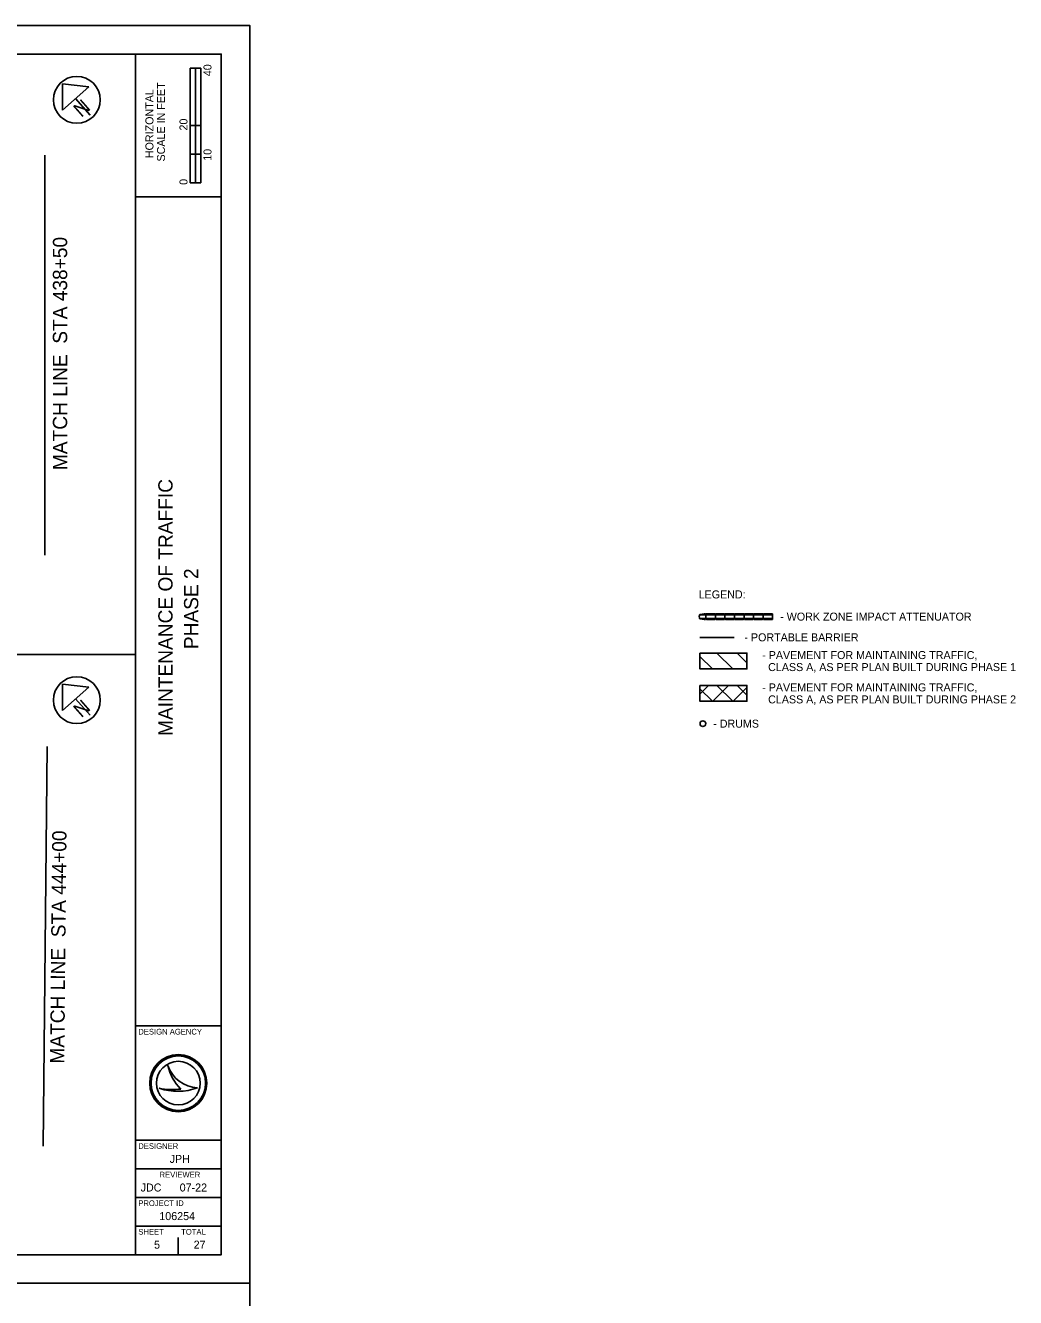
# Model space of a CAD drawing. Extents: x 0 to 5770, y -1320 to 440.
# Drawn here: x 601.5 to 948, y -5 to 440 of the extents above; entities that cross this region are included whole.
import ezdxf

# ---------------------------------------------------------------- set-up
doc = ezdxf.new("R2010")
doc.units = 0
for name, color, linetype in [('_CIVIL_CONSTRUCTION', 7, 'Continuous'), ('BR_X_Sub_Backwall', 7, 'Continuous'), ('GE_P_Alignment', 7, 'Continuous'), ('GE_P_Alignment_100_Bearings', 7, 'Continuous'), ('GE_P_Alignment_100_Cardinal_Points', 7, 'Continuous'), ('GE_P_Alignment_100_Curve_Data', 7, 'Continuous'), ('GE_P_Alignment_100_Stations', 7, 'Continuous'), ('HY_X_Water_Edge', 7, 'Continuous'), ('PV_X_EOP', 7, 'Continuous')]:
    doc.layers.add(name, color=color, linetype=linetype)

msp = doc.modelspace()

# ---------------------------------------------------------------- linework, layer by layer
at = {"layer": '_CIVIL_CONSTRUCTION'}
for points in [[(0, 0), (680, 0), (680, 440), (0, 440)], [(0, -440), (680, -440), (680, 0), (0, 0)]]:
    msp.add_lwpolyline(points, close=True, dxfattribs=at)
at = {"layer": 'BR_X_Sub_Backwall'}
msp.add_line((849.52, 225.95), (837.52, 225.95), dxfattribs=at)
at = {"layer": 'GE_P_Alignment'}
for p, q in [((640, 10), (640, 430)), ((640, 380), (670, 380)), ((640, 90), (670, 90)), ((640, 50), (670, 50)), ((640, 40), (670, 40)), ((640, 30), (670, 30)), ((640, 20), (670, 20))]:
    msp.add_line(p, q, dxfattribs=at)
msp.add_lwpolyline([(30, 430), (670, 430), (670, 10), (30, 10)], close=True, dxfattribs=at)
at = {"layer": 'GE_P_Alignment_100_Bearings'}
for p, q in [((659.13, 385), (659.13, 425)), ((662.88, 425), (659.13, 425)), ((659.13, 405), (659.13, 425)), ((659.13, 425), (661, 425)), ((661, 425), (661.02, 425)), ((661.02, 425), (661.02, 405)), ((662.88, 425), (662.88, 385)), ((661.02, 405), (659.13, 405)), ((662.87, 405), (661, 405)), ((661, 405), (661, 395)), ((662.87, 395), (662.87, 405)), ((661, 395), (659.13, 395)), ((659.13, 395), (659.13, 385)), ((661, 385), (661, 395)), ((661, 395), (662.87, 395)), ((662.88, 385), (659.13, 385)), ((659.13, 385), (661, 385)), ((651.35, 76.19), (651.35, 76.19)), ((648.34, 68.19), (648.34, 68.19)), ((655, 70), (655, 70)), ((661.75, 68.37), (661.75, 68.37)), ((647.5, 13.5), (647.5, 13.5)), ((655, 10), (655, 16))]:
    msp.add_line(p, q, dxfattribs=at)
for radius in [10, 9.54, 9.54, 7.64]:
    msp.add_circle((655, 70), radius, dxfattribs=at)
for centre, radius, start, end in [((662.32, 79.95), 11.6, 198.9257, 198.9319), ((666.93, 79.4), 15.91, 191.6379, 191.6421), ((662.32, 79.95), 11.6, 198.9319, 267.1657), ((666.93, 79.4), 15.91, 191.6421, 226.0947), ((654.79, 87.4), 20.26, 251.4576, 290.0832), ((652.96, 93.09), 25.32, 259.4964, 259.4995), ((654.79, 87.4), 20.26, 251.4527, 251.4576), ((652.96, 93.09), 25.32, 259.4995, 276.6672)]:
    msp.add_arc(centre, radius, start, end, dxfattribs=at)
at = {"layer": 'GE_P_Alignment_100_Cardinal_Points'}
for p, q in [((614.53, 419.6), (614.42, 410.41)), ((614.42, 410.41), (623.66, 418.54)), ((623.66, 418.54), (614.53, 419.6)), ((619.04, 414.48), (624.15, 408.67)), ((30, 220), (640, 220)), ((614.53, 209.6), (614.42, 200.41)), ((623.66, 208.54), (614.53, 209.6)), ((614.42, 200.41), (623.66, 208.54)), ((619.04, 204.48), (624.15, 198.67))]:
    msp.add_line(p, q, dxfattribs=at)
for centre in [(619.47, 413.99), (619.47, 203.99)]:
    msp.add_circle(centre, 8.2, dxfattribs=at)
at = {"layer": 'GE_P_Alignment_100_Curve_Data'}
for p, q in [((608.28, 394.64), (608.28, 254.64)), ((607.71, 47.99), (609.09, 187.71))]:
    msp.add_line(p, q, dxfattribs=at)
for points in [[(837.52, 220.42), (853.95, 220.42), (853.95, 214.88), (837.52, 214.88)], [(837.52, 209.11), (853.95, 209.11), (853.95, 203.57), (837.52, 203.57)]]:
    msp.add_lwpolyline(points, close=True, dxfattribs=at)
at = {"layer": 'GE_P_Alignment_100_Stations'}
for p, q in [((837.52, 219.3), (841.94, 214.88)), ((843.48, 220.42), (849.01, 214.88)), ((850.55, 220.42), (853.95, 217.01)), ((837.52, 206.11), (840.52, 209.11)), ((837.52, 207.99), (841.94, 203.57)), ((842.06, 203.57), (847.59, 209.11)), ((843.48, 209.11), (849.01, 203.57)), ((849.13, 203.57), (853.95, 208.4)), ((850.55, 209.11), (853.95, 205.7))]:
    msp.add_line(p, q, dxfattribs=at)
at = {"layer": 'HY_X_Water_Edge'}
for centre in [(619.47, 413.99), (619.47, 203.99)]:
    msp.add_circle(centre, 8.2, dxfattribs=at)
at = {"layer": 'PV_X_EOP'}
for p, q in [((837.47, 233.87), (862.96, 233.87)), ((862.96, 232.54), (837.47, 232.54)), ((839.02, 234.2), (837.52, 233.95)), ((839.02, 232.2), (837.52, 232.45)), ((839.02, 234.2), (839.46, 234.2)), ((839.46, 232.2), (839.02, 232.2)), ((839.63, 234.04), (839.46, 234.2)), ((839.63, 232.37), (839.46, 232.2)), ((839.79, 234.2), (839.63, 234.04)), ((839.63, 232.37), (839.63, 234.04)), ((839.79, 232.2), (839.63, 232.37)), ((839.79, 234.2), (842.79, 234.2)), ((842.79, 232.2), (839.79, 232.2)), ((842.96, 234.04), (842.79, 234.2)), ((842.96, 232.37), (842.79, 232.2)), ((843.13, 234.2), (842.96, 234.04)), ((842.96, 232.37), (842.96, 234.04)), ((843.13, 232.2), (842.96, 232.37)), ((843.13, 234.2), (846.13, 234.2)), ((846.13, 232.2), (843.13, 232.2)), ((846.29, 234.04), (846.13, 234.2)), ((846.29, 232.37), (846.13, 232.2)), ((846.46, 234.2), (846.29, 234.04)), ((846.29, 232.37), (846.29, 234.04)), ((846.46, 232.2), (846.29, 232.37)), ((846.46, 234.2), (849.46, 234.2)), ((846.46, 232.2), (849.46, 232.2)), ((849.63, 234.04), (849.46, 234.2)), ((849.63, 232.37), (849.46, 232.2)), ((849.79, 234.2), (849.63, 234.04)), ((849.63, 232.37), (849.63, 234.04)), ((849.79, 232.2), (849.63, 232.37)), ((849.79, 234.2), (852.79, 234.2)), ((849.79, 232.2), (852.79, 232.2)), ((852.96, 234.04), (852.79, 234.2)), ((852.96, 232.37), (852.79, 232.2)), ((853.13, 234.2), (852.96, 234.04)), ((852.96, 232.37), (852.96, 234.04)), ((853.13, 232.2), (852.96, 232.37)), ((853.13, 234.2), (856.13, 234.2)), ((853.13, 232.2), (856.13, 232.2)), ((856.29, 234.04), (856.13, 234.2)), ((856.29, 232.37), (856.13, 232.2)), ((856.46, 234.2), (856.29, 234.04)), ((856.29, 232.37), (856.29, 234.04)), ((856.46, 232.2), (856.29, 232.37)), ((856.46, 234.2), (859.46, 234.2)), ((856.46, 232.2), (859.46, 232.2)), ((859.63, 234.04), (859.46, 234.2)), ((859.63, 232.37), (859.46, 232.2)), ((859.79, 234.2), (859.63, 234.04)), ((859.63, 232.37), (859.63, 234.04)), ((859.79, 232.2), (859.63, 232.37)), ((859.79, 234.2), (862.96, 234.2)), ((859.79, 232.2), (862.96, 232.2)), ((862.96, 232.2), (862.96, 234.2))]:
    msp.add_line(p, q, dxfattribs=at)
msp.add_circle((838.57, 195.76), 1, dxfattribs=at)
msp.add_arc((838.63, 233.2), 1.34, 145.8243, 214.1757, dxfattribs=at)

# ---------------------------------------------------------------- texts
at = {"layer": 'GE_P_Alignment_100_Bearings'}
for s, height, rotation, p in [('40', 2.8, 90, (666.61, 422.25)), ('SCALE IN FEET', 2.8, 90, (650.35, 392.41)), ('HORIZONTAL', 2.8, 90, (646.3, 393.58)), ('20', 2.8, 90, (658.21, 403.25)), ('10', 2.8, 90, (666.61, 392.65)), ('0', 2.8, 90, (658.21, 384.23)), ('MATCH LINE  STA 438+50', 5, 90, (616.11, 284.46)), ('MAINTENANCE OF TRAFFIC', 5, 90, (653, 191.45)), ('PHASE 2', 5, 90, (662, 221.83)), ('MATCH LINE  STA 444+00', 5, 89.4369, (615.09, 76.81))]:
    msp.add_text(s, height=height, rotation=rotation, dxfattribs=at).set_placement(p)
for s, height, p in [('DESIGN AGENCY', 2, (641, 87)), ('DESIGNER', 2, (641, 47)), ('JPH', 2.8, (651.97, 42.1)), ('REVIEWER', 2, (648.44, 37)), ('JDC', 2.8, (641.82, 32.1)), ('07-22', 2.8, (655.48, 32.1)), ('PROJECT ID', 2, (641, 27)), ('106254', 2.8, (648.36, 22.1)), ('SHEET', 2, (641, 17)), ('TOTAL', 2, (656, 17)), ('5', 2.8, (646.51, 12.1)), ('27', 2.8, (660.37, 12.1))]:
    msp.add_text(s, height=height, dxfattribs=at).set_placement(p)
at = {"layer": 'GE_P_Alignment_100_Cardinal_Points'}
for p in [(621.04, 407.62), (621.04, 197.62)]:
    msp.add_text('N', height=5, rotation=41.3425, dxfattribs=at).set_placement(p)
at = {"layer": 'GE_P_Alignment_100_Curve_Data'}
for s, p in [('LEGEND:', (837.09, 239.57)), ('- WORK ZONE IMPACT ATTENUATOR', (865.62, 231.8)), ('- PORTABLE BARRIER', (853.1, 224.55)), ('- PAVEMENT FOR MAINTAINING TRAFFIC,', (859.32, 218.35)), ('  CLASS A, AS PER PLAN BUILT DURING PHASE 1', (859.32, 214.15)), ('- PAVEMENT FOR MAINTAINING TRAFFIC,', (859.32, 207.04)), ('  CLASS A, AS PER PLAN BUILT DURING PHASE 2', (859.32, 202.84)), ('- DRUMS', (842.19, 194.36))]:
    msp.add_text(s, height=2.8, dxfattribs=at).set_placement(p)

doc.saveas('drawing.dxf')
